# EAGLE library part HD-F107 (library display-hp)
LED DISPLAY + - 1/2 character, decimal point right
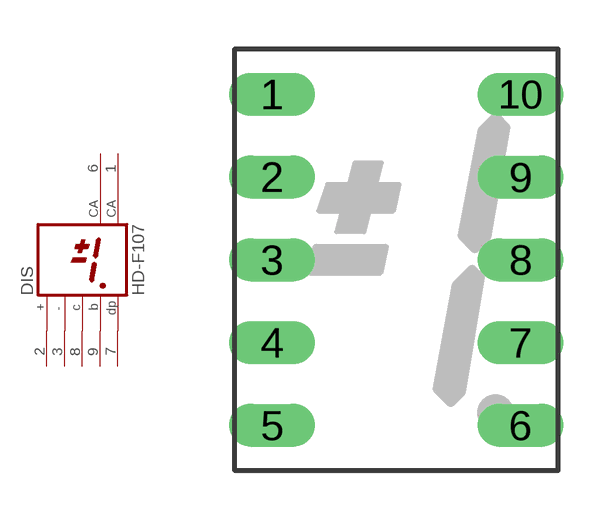
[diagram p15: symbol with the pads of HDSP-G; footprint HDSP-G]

Designator prefix DIS

## HD-F107 (OC_FARNELL: unknown; OC_NEWARK: unknown)  [HDSP-G]
1  CA  pas
2  +  pas
3  -  pas
6  CA  pas
7  DP  pas
8  C  pas
9  B  pas

## Footprint HDSP-G (pad centres in mm)
LED DISPLAY 10-mm + - 1/2 character, decimal point right
drill 0.813 long: 1 -3.81,5.08; 2 -3.81,2.54; 3 -3.81,0; 4 -3.81,-2.54; 5 -3.81,-5.08; 6 3.81,-5.08; 7 3.81,-2.54; 8 3.81,0; 9 3.81,2.54; 10 3.81,5.08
